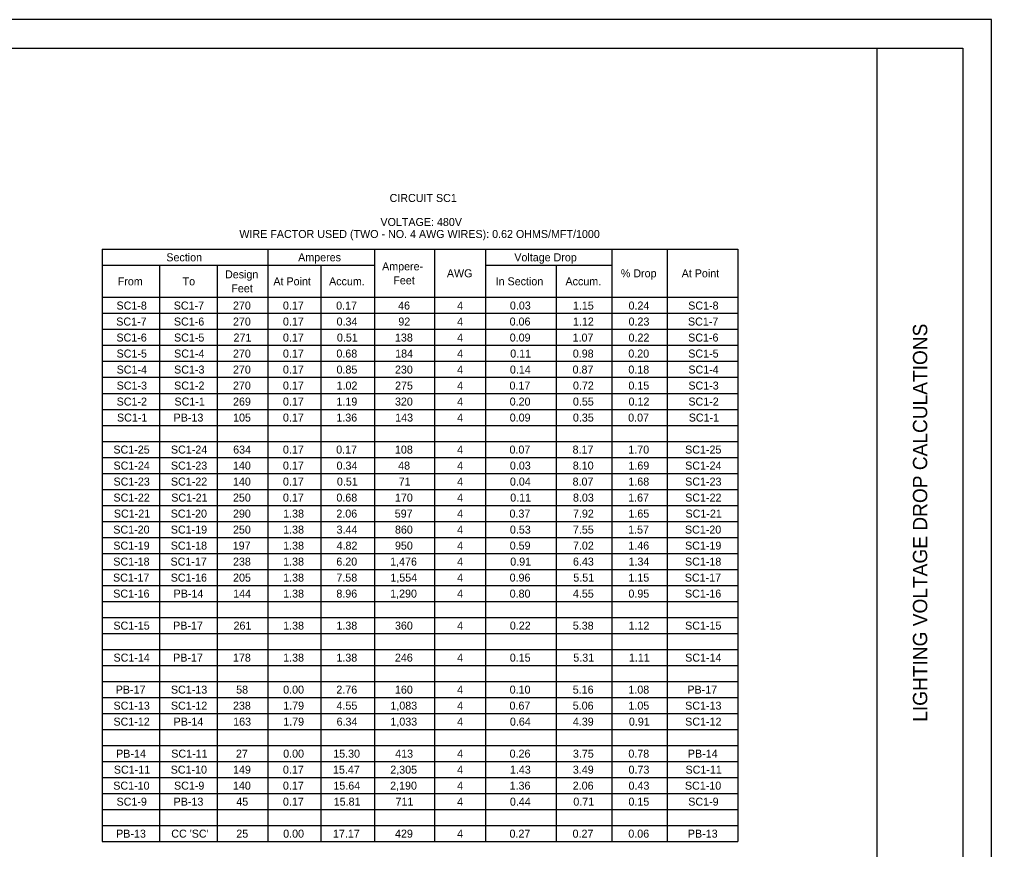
# Model space of a CAD drawing. Extents: x 0 to 34, y 0 to 22.
# Drawn here: x 17 to 34, y 7.48 to 22 of the extents above; entities that cross this region are included whole.
import ezdxf

# ---------------------------------------------------------------- set-up
doc = ezdxf.new("R2010")
doc.units = 0
for name, color, linetype in [('SH_Border', 7, 'Continuous'), ('SH_Cut_Line', 7, 'Continuous'), ('SH_Data', 7, 'Continuous'), ('SH_Text', 7, 'Continuous')]:
    doc.layers.add(name, color=color, linetype=linetype)

msp = doc.modelspace()

# ---------------------------------------------------------------- linework, layer by layer
at = {"layer": 'SH_Border'}
msp.add_line((32, 0.5), (32, 21.5), dxfattribs=at)
msp.add_lwpolyline([(1.5, 21.5), (33.5, 21.5), (33.5, 0.5), (1.5, 0.5)], close=True, dxfattribs=at)
at = {"layer": 'SH_Cut_Line'}
msp.add_lwpolyline([(0, 0), (34, 0), (34, 22), (0, 22)], close=True, dxfattribs=at)
at = {"layer": 'SH_Text'}
for p, q in [((18.447, 17.978), (29.565, 17.978)), ((18.447, 17.978), (18.447, 7.618)), ((21.346, 17.978), (21.346, 7.618)), ((23.207, 17.978), (23.207, 7.618)), ((24.261, 17.978), (24.261, 7.618)), ((25.151, 17.978), (25.151, 7.618)), ((27.358, 17.978), (27.358, 7.618)), ((28.329, 17.978), (28.329, 7.618)), ((29.565, 17.978), (29.565, 7.618)), ((18.447, 17.698), (23.207, 17.698)), ((19.452, 17.698), (19.452, 7.618)), ((20.456, 17.698), (20.456, 7.618)), ((22.268, 17.698), (22.268, 7.618)), ((25.151, 17.698), (27.358, 17.698)), ((26.386, 17.698), (26.386, 7.618)), ((18.447, 17.138), (29.565, 17.138)), ((18.447, 16.858), (29.565, 16.858)), ((18.447, 16.578), (29.565, 16.578)), ((18.447, 16.298), (29.565, 16.298)), ((18.447, 16.018), (29.565, 16.018)), ((18.447, 15.738), (29.565, 15.738)), ((18.447, 15.458), (29.565, 15.458)), ((18.447, 15.178), (29.565, 15.178)), ((18.447, 14.898), (29.565, 14.898)), ((18.447, 14.618), (29.565, 14.618)), ((18.447, 14.338), (29.565, 14.338)), ((18.447, 14.058), (29.565, 14.058)), ((18.447, 13.778), (29.565, 13.778)), ((18.447, 13.498), (29.565, 13.498)), ((18.447, 13.218), (29.565, 13.218)), ((18.447, 12.938), (29.565, 12.938)), ((18.447, 12.658), (29.565, 12.658)), ((18.447, 12.378), (29.565, 12.378)), ((18.447, 12.098), (29.565, 12.098)), ((18.447, 11.818), (29.565, 11.818)), ((18.447, 11.538), (29.565, 11.538)), ((18.447, 11.258), (29.565, 11.258)), ((18.447, 10.978), (29.565, 10.978)), ((18.447, 10.698), (29.565, 10.698)), ((18.447, 10.418), (29.565, 10.418)), ((18.447, 10.138), (29.565, 10.138)), ((18.447, 9.858), (29.565, 9.858)), ((18.447, 9.578), (29.565, 9.578)), ((18.447, 9.298), (29.565, 9.298)), ((18.447, 9.018), (29.565, 9.018)), ((18.447, 8.738), (29.565, 8.738)), ((18.447, 8.458), (29.565, 8.458)), ((18.447, 8.178), (29.565, 8.178)), ((18.447, 7.898), (29.565, 7.898)), ((18.447, 7.618), (29.565, 7.618))]:
    msp.add_line(p, q, dxfattribs=at)

# ---------------------------------------------------------------- texts
at = {"layer": 'SH_Data'}
msp.add_text('LIGHTING VOLTAGE DROP CALCULATIONS', height=0.25, rotation=90, dxfattribs=at).set_placement((32.875, 9.711))
at = {"layer": 'SH_Text'}
for s, p in [('CIRCUIT SC1', (23.473, 18.806)), ('VOLTAGE: 480V', (23.313, 18.386)), ('WIRE FACTOR USED (TWO - NO. 4 AWG WIRES): 0.62 OHMS/MFT/1000', (20.846, 18.176)), ('Section', (19.569, 17.768)), ('Amperes', (21.874, 17.768)), ('Voltage Drop', (25.654, 17.768)), ('Ampere-', (23.342, 17.61)), ('Design', (20.595, 17.47)), ('AWG', (24.475, 17.488)), ('% Drop', (27.517, 17.488)), ('At Point', (28.581, 17.488)), ('From', (18.719, 17.348)), ('To', (19.853, 17.348)), ('Feet', (20.705, 17.225)), ('At Point', (21.441, 17.348)), ('Accum.', (22.415, 17.348)), ('Feet', (23.538, 17.365)), ('In Section', (25.328, 17.348)), ('Accum.', (26.549, 17.348)), ('SC1-8', (18.697, 16.924)), ('SC1-7', (19.698, 16.924)), ('270', (20.734, 16.924)), ('0.17', (21.608, 16.924)), ('0.17', (22.539, 16.924)), ('46', (23.622, 16.924)), ('4', (24.654, 16.924)), ('0.03', (25.577, 16.924)), ('1.15', (26.679, 16.924)), ('0.24', (27.652, 16.924)), ('SC1-8', (28.695, 16.924)), ('SC1-7', (18.693, 16.644)), ('SC1-6', (19.701, 16.644)), ('270', (20.734, 16.644)), ('0.17', (21.608, 16.644)), ('0.34', (22.546, 16.644)), ('92', (23.626, 16.644)), ('4', (24.654, 16.644)), ('0.06', (25.572, 16.644)), ('1.12', (26.68, 16.644)), ('0.23', (27.652, 16.644)), ('SC1-7', (28.691, 16.644)), ('SC1-6', (18.696, 16.364)), ('SC1-5', (19.703, 16.364)), ('271', (20.744, 16.364)), ('0.17', (21.608, 16.364)), ('0.51', (22.552, 16.364)), ('138', (23.567, 16.364)), ('4', (24.654, 16.364)), ('0.09', (25.574, 16.364)), ('1.07', (26.673, 16.364)), ('0.22', (27.652, 16.364)), ('SC1-6', (28.694, 16.364)), ('SC1-5', (18.699, 16.084)), ('SC1-4', (19.705, 16.084)), ('270', (20.734, 16.084)), ('0.17', (21.608, 16.084)), ('0.68', (22.543, 16.084)), ('184', (23.571, 16.084)), ('4', (24.654, 16.084)), ('0.11', (25.583, 16.084)), ('0.98', (26.677, 16.084)), ('0.20', (27.648, 16.084)), ('SC1-5', (28.696, 16.084)), ('SC1-4', (18.7, 15.804)), ('SC1-3', (19.705, 15.804)), ('270', (20.734, 15.804)), ('0.17', (21.608, 15.804)), ('0.85', (22.545, 15.804)), ('230', (23.567, 15.804)), ('4', (24.654, 15.804)), ('0.14', (25.577, 15.804)), ('0.87', (26.673, 15.804)), ('0.18', (27.649, 15.804)), ('SC1-4', (28.698, 15.804)), ('SC1-3', (18.7, 15.524)), ('SC1-2', (19.705, 15.524)), ('270', (20.734, 15.524)), ('0.17', (21.608, 15.524)), ('1.02', (22.546, 15.524)), ('275', (23.569, 15.524)), ('4', (24.654, 15.524)), ('0.17', (25.57, 15.524)), ('0.72', (26.68, 15.524)), ('0.15', (27.65, 15.524)), ('SC1-3', (28.698, 15.524)), ('SC1-2', (18.7, 15.244)), ('SC1-1', (19.711, 15.244)), ('269', (20.735, 15.244)), ('0.17', (21.608, 15.244)), ('1.19', (22.544, 15.244)), ('320', (23.567, 15.244)), ('4', (24.654, 15.244)), ('0.20', (25.573, 15.244)), ('0.55', (26.679, 15.244)), ('0.12', (27.652, 15.244)), ('SC1-2', (28.698, 15.244)), ('SC1-1', (18.706, 14.964)), ('PB-13', (19.696, 14.964)), ('105', (20.736, 14.964)), ('0.17', (21.608, 14.964)), ('1.36', (22.542, 14.964)), ('143', (23.571, 14.964)), ('4', (24.654, 14.964)), ('0.09', (25.574, 14.964)), ('0.35', (26.679, 14.964)), ('0.07', (27.645, 14.964)), ('SC1-1', (28.704, 14.964)), ('SC1-25', (18.643, 14.404)), ('SC1-24', (19.649, 14.404)), ('634', (20.738, 14.404)), ('0.17', (21.608, 14.404)), ('0.17', (22.539, 14.404)), ('108', (23.567, 14.404)), ('4', (24.654, 14.404)), ('0.07', (25.57, 14.404)), ('8.17', (26.673, 14.404)), ('1.70', (27.648, 14.404)), ('SC1-25', (28.641, 14.404)), ('SC1-24', (18.645, 14.124)), ('SC1-23', (19.649, 14.124)), ('140', (20.734, 14.124)), ('0.17', (21.608, 14.124)), ('0.34', (22.546, 14.124)), ('48', (23.623, 14.124)), ('4', (24.654, 14.124)), ('0.03', (25.577, 14.124)), ('8.10', (26.677, 14.124)), ('1.69', (27.65, 14.124)), ('SC1-24', (28.642, 14.124)), ('SC1-23', (18.645, 13.844)), ('SC1-22', (19.649, 13.844)), ('140', (20.734, 13.844)), ('0.17', (21.608, 13.844)), ('0.51', (22.552, 13.844)), ('71', (23.632, 13.844)), ('4', (24.654, 13.844)), ('0.04', (25.577, 13.844)), ('8.07', (26.673, 13.844)), ('1.68', (27.649, 13.844)), ('SC1-23', (28.642, 13.844)), ('SC1-22', (18.644, 13.564)), ('SC1-21', (19.655, 13.564)), ('250', (20.734, 13.564)), ('0.17', (21.608, 13.564)), ('0.68', (22.543, 13.564)), ('170', (23.567, 13.564)), ('4', (24.654, 13.564)), ('0.11', (25.583, 13.564)), ('8.03', (26.68, 13.564)), ('1.67', (27.645, 13.564)), ('SC1-22', (28.642, 13.564)), ('SC1-21', (18.651, 13.284)), ('SC1-20', (19.645, 13.284)), ('290', (20.734, 13.284)), ('1.38', (21.612, 13.284)), ('2.06', (22.542, 13.284)), ('597', (23.563, 13.284)), ('4', (24.654, 13.284)), ('0.37', (25.57, 13.284)), ('7.92', (26.68, 13.284)), ('1.65', (27.65, 13.284)), ('SC1-21', (28.648, 13.284)), ('SC1-20', (18.641, 13.004)), ('SC1-19', (19.647, 13.004)), ('250', (20.734, 13.004)), ('1.38', (21.612, 13.004)), ('3.44', (22.546, 13.004)), ('860', (23.567, 13.004)), ('4', (24.654, 13.004)), ('0.53', (25.577, 13.004)), ('7.55', (26.679, 13.004)), ('1.57', (27.645, 13.004)), ('SC1-20', (28.638, 13.004)), ('SC1-19', (18.642, 12.724)), ('SC1-18', (19.646, 12.724)), ('197', (20.73, 12.724)), ('1.38', (21.612, 12.724)), ('4.82', (22.546, 12.724)), ('950', (23.567, 12.724)), ('4', (24.654, 12.724)), ('0.59', (25.574, 12.724)), ('7.02', (26.68, 12.724)), ('1.46', (27.648, 12.724)), ('SC1-19', (28.64, 12.724)), ('SC1-18', (18.641, 12.444)), ('SC1-17', (19.642, 12.444)), ('238', (20.734, 12.444)), ('1.38', (21.612, 12.444)), ('6.20', (22.542, 12.444)), ('1,476', (23.483, 12.444)), ('4', (24.654, 12.444)), ('0.91', (25.583, 12.444)), ('6.43', (26.68, 12.444)), ('1.34', (27.652, 12.444)), ('SC1-18', (28.639, 12.444)), ('SC1-17', (18.637, 12.164)), ('SC1-16', (19.645, 12.164)), ('205', (20.736, 12.164)), ('1.38', (21.612, 12.164)), ('7.58', (22.543, 12.164)), ('1,554', (23.487, 12.164)), ('4', (24.654, 12.164)), ('0.96', (25.572, 12.164)), ('5.51', (26.686, 12.164)), ('1.15', (27.65, 12.164)), ('SC1-17', (28.635, 12.164)), ('SC1-16', (18.64, 11.884)), ('PB-14', (19.696, 11.884)), ('144', (20.738, 11.884)), ('1.38', (21.612, 11.884)), ('8.96', (22.542, 11.884)), ('1,290', (23.483, 11.884)), ('4', (24.654, 11.884)), ('0.80', (25.573, 11.884)), ('4.55', (26.679, 11.884)), ('0.95', (27.65, 11.884)), ('SC1-16', (28.638, 11.884)), ('SC1-15', (18.643, 11.324)), ('PB-17', (19.688, 11.324)), ('261', (20.744, 11.324)), ('1.38', (21.612, 11.324)), ('1.38', (22.543, 11.324)), ('360', (23.567, 11.324)), ('4', (24.654, 11.324)), ('0.22', (25.576, 11.324)), ('5.38', (26.677, 11.324)), ('1.12', (27.652, 11.324)), ('SC1-15', (28.641, 11.324)), ('SC1-14', (18.645, 10.764)), ('PB-17', (19.688, 10.764)), ('178', (20.734, 10.764)), ('1.38', (21.612, 10.764)), ('1.38', (22.543, 10.764)), ('246', (23.566, 10.764)), ('4', (24.654, 10.764)), ('0.15', (25.575, 10.764)), ('5.31', (26.686, 10.764)), ('1.11', (27.658, 10.764)), ('SC1-14', (28.642, 10.764)), ('PB-17', (18.684, 10.204)), ('SC1-13', (19.649, 10.204)), ('58', (20.79, 10.204)), ('0.00', (21.612, 10.204)), ('2.76', (22.542, 10.204)), ('160', (23.567, 10.204)), ('4', (24.654, 10.204)), ('0.10', (25.573, 10.204)), ('5.16', (26.676, 10.204)), ('1.08', (27.649, 10.204)), ('PB-17', (28.681, 10.204)), ('SC1-13', (18.645, 9.924)), ('SC1-12', (19.649, 9.924)), ('238', (20.734, 9.924)), ('1.79', (21.613, 9.924)), ('4.55', (22.545, 9.924)), ('1,083', (23.487, 9.924)), ('4', (24.654, 9.924)), ('0.67', (25.57, 9.924)), ('5.06', (26.676, 9.924)), ('1.05', (27.65, 9.924)), ('SC1-13', (28.642, 9.924)), ('SC1-12', (18.644, 9.644)), ('PB-14', (19.696, 9.644)), ('163', (20.738, 9.644)), ('1.79', (21.613, 9.644)), ('6.34', (22.546, 9.644)), ('1,033', (23.487, 9.644)), ('4', (24.654, 9.644)), ('0.64', (25.577, 9.644)), ('4.39', (26.678, 9.644)), ('0.91', (27.658, 9.644)), ('SC1-12', (28.642, 9.644)), ('PB-14', (18.691, 9.084)), ('SC1-11', (19.655, 9.084)), ('27', (20.786, 9.084)), ('0.00', (21.612, 9.084)), ('15.30', (22.487, 9.084)), ('413', (23.571, 9.084)), ('4', (24.654, 9.084)), ('0.26', (25.572, 9.084)), ('3.75', (26.679, 9.084)), ('0.78', (27.649, 9.084)), ('PB-14', (28.689, 9.084)), ('SC1-11', (18.651, 8.804)), ('SC1-10', (19.645, 8.804)), ('149', (20.735, 8.804)), ('0.17', (21.608, 8.804)), ('15.47', (22.483, 8.804)), ('2,305', (23.485, 8.804)), ('4', (24.654, 8.804)), ('1.43', (25.577, 8.804)), ('3.49', (26.678, 8.804)), ('0.73', (27.652, 8.804)), ('SC1-11', (28.648, 8.804)), ('SC1-10', (18.641, 8.524)), ('SC1-9', (19.703, 8.524)), ('140', (20.734, 8.524)), ('0.17', (21.608, 8.524)), ('15.64', (22.49, 8.524)), ('2,190', (23.483, 8.524)), ('4', (24.654, 8.524)), ('1.36', (25.572, 8.524)), ('2.06', (26.676, 8.524)), ('0.43', (27.652, 8.524)), ('SC1-10', (28.638, 8.524)), ('SC1-9', (18.698, 8.244)), ('PB-13', (19.696, 8.244)), ('45', (20.792, 8.244)), ('0.17', (21.608, 8.244)), ('15.81', (22.496, 8.244)), ('711', (23.577, 8.244)), ('4', (24.654, 8.244)), ('0.44', (25.577, 8.244)), ('0.71', (26.686, 8.244)), ('0.15', (27.65, 8.244)), ('SC1-9', (28.696, 8.244)), ('PB-13', (18.691, 7.684)), ("CC 'SC'", (19.655, 7.684)), ('25', (20.792, 7.684)), ('0.00', (21.612, 7.684)), ('17.17', (22.483, 7.684)), ('429', (23.568, 7.684)), ('4', (24.654, 7.684)), ('0.27', (25.57, 7.684)), ('0.27', (26.673, 7.684)), ('0.06', (27.648, 7.684)), ('PB-13', (28.689, 7.684))]:
    msp.add_text(s, height=0.14, dxfattribs=at).set_placement(p)

doc.saveas('drawing.dxf')
